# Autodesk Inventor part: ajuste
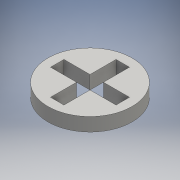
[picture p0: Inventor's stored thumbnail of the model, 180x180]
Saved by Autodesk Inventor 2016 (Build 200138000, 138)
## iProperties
Created: 2016-06
Part Number: ajuste
Material: Genérico
Document SubType Name: Modeling
Designer: adm
Density: 1 g/cm^3
Appearance: Valor por defecto
Author: adm
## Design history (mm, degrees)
sketch "Boceto1"
  geometry: L1 (-2, -9.75)-(2, -9.75); L2 (2, -9.75)-(2, 9.75); L3 (2, 9.75)-(-2, 9.75); L4 (-2, 9.75)-(-2, -9.75); L5 (-2, -9.75)-(2, 9.75); L6 (2, -9.75)-(-2, 9.75); L7 (-9.75, -2)-(9.75, -2); L8 (9.75, -2)-(9.75, 2); L9 (9.75, 2)-(-9.75, 2); L10 (-9.75, 2)-(-9.75, -2); L11 (-9.75, -2)-(9.75, 2); L12 (9.75, -2)-(-9.75, 2); C1 r 12.5 at (0, 0); 1 further point
  constraints: 24 end point, 4 midpoint, 4 parallel, 2 horizontal, 2 perpendicular, 1 centre point, 1 coincident
  dimensions: "d0" = 25 diameter of C1; "d1" = 4 distance of L3.end L2.end; "d2" = 19.5 distance of L1.end L2.end; "d3" = 19.5 distance of L9.end L8.end; "d4" = 4 distance of L8.end L7.end
extrude "Extrusión1" new body sketch "Boceto1" distance "d5" = 4; taper "d6" = 0 deg
node "Sólido1"
